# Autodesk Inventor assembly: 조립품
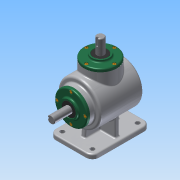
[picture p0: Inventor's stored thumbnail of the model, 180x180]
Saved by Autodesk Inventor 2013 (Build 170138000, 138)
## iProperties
Created: 2016-09
Part Number: 조립품
Document SubType Name: Assembly
Designer: Administrator
Author: Administrator
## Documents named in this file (14)
- C:\Users\Administrator\Desktop\460908V1013\조립품.iam
- C:\Users\Administrator\Desktop\460908V1013\본체.ipt
- C:\Users\Administrator\Desktop\460908V1013\메인 축.ipt
- 메인 축.ipt
- C:\Users\Administrator\Desktop\460908V1013\키 5x5.ipt
- C:\Users\Administrator\Desktop\460908V1013\메인 베벨기어.ipt
- C:\Users\Administrator\Desktop\460908V1013\서브 베벨기어.ipt
- C:\Users\Administrator\Desktop\460908V1013\서브 축.ipt
- 서브 축.ipt
- C:\Users\Administrator\Desktop\460908V1013\커버.ipt
- C:\Users\Administrator\Desktop\460908V1013\키 4x4.ipt
- C:\Users\Administrator\Desktop\460908V1013\베어링 6203.ipt
- C:\Users\Administrator\Desktop\460908V1013\오일실 17 32 8.ipt
- C:\Users\Administrator\Desktop\460908V1013\M4.ipt
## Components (8 placed, 1 different names)
1. M4:2 — 각도:3
2. M4:3
3. M4:4
4. M4:5
5. M4:1 — 각도:2
6. M4:6
7. M4:7
8. M4:8
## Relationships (2: Angle 2)
- 각도:2 [Angle]: M4:1
- 각도:3 [Angle]: M4:2
